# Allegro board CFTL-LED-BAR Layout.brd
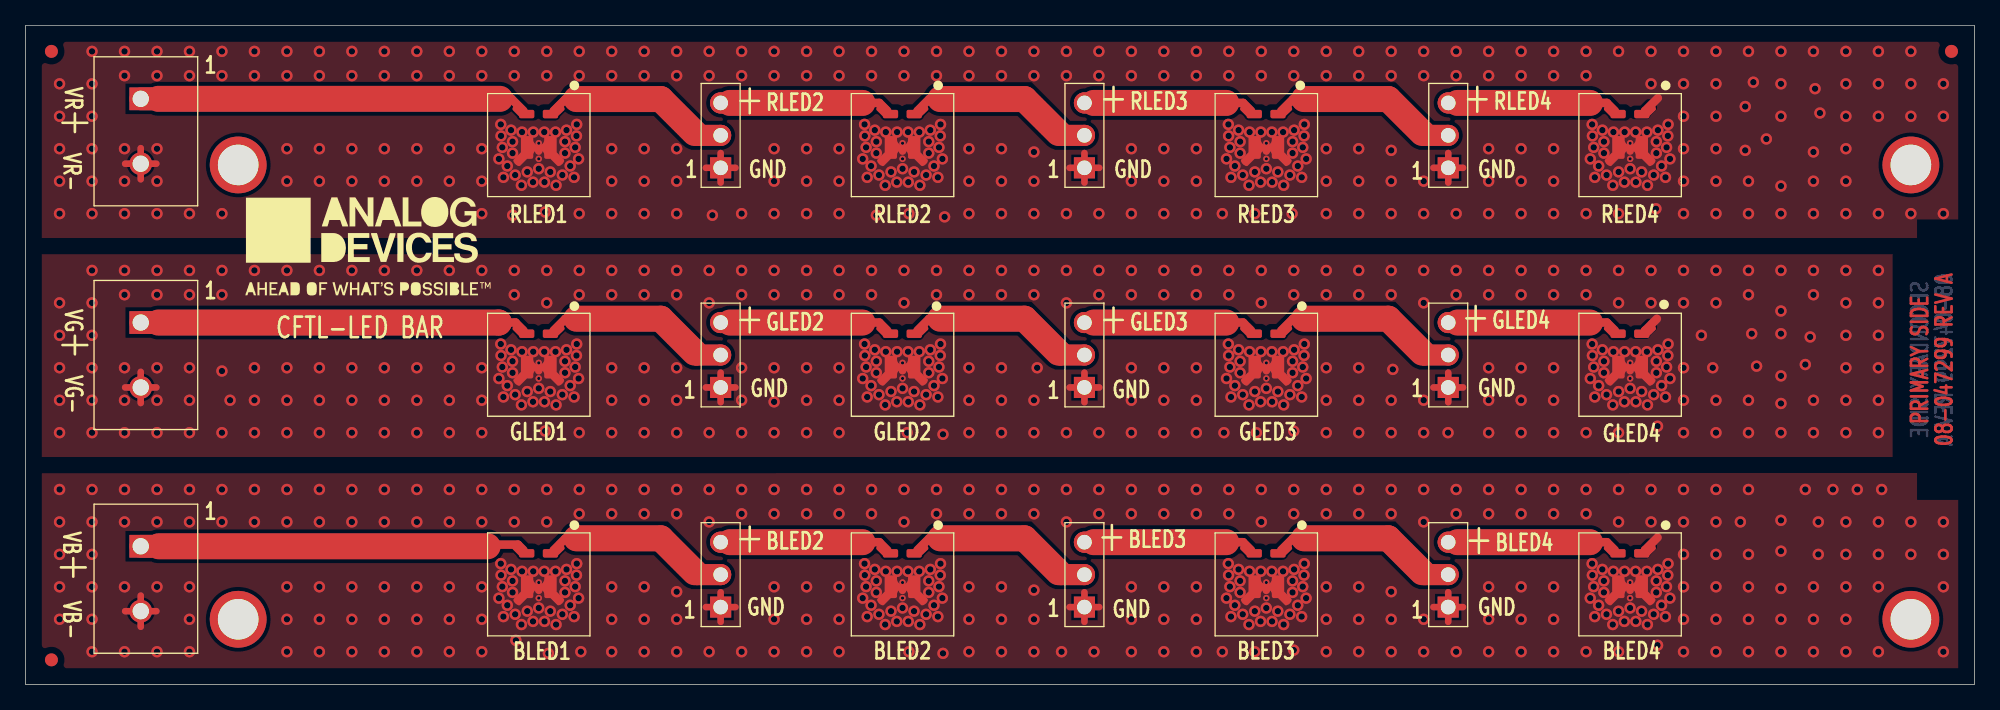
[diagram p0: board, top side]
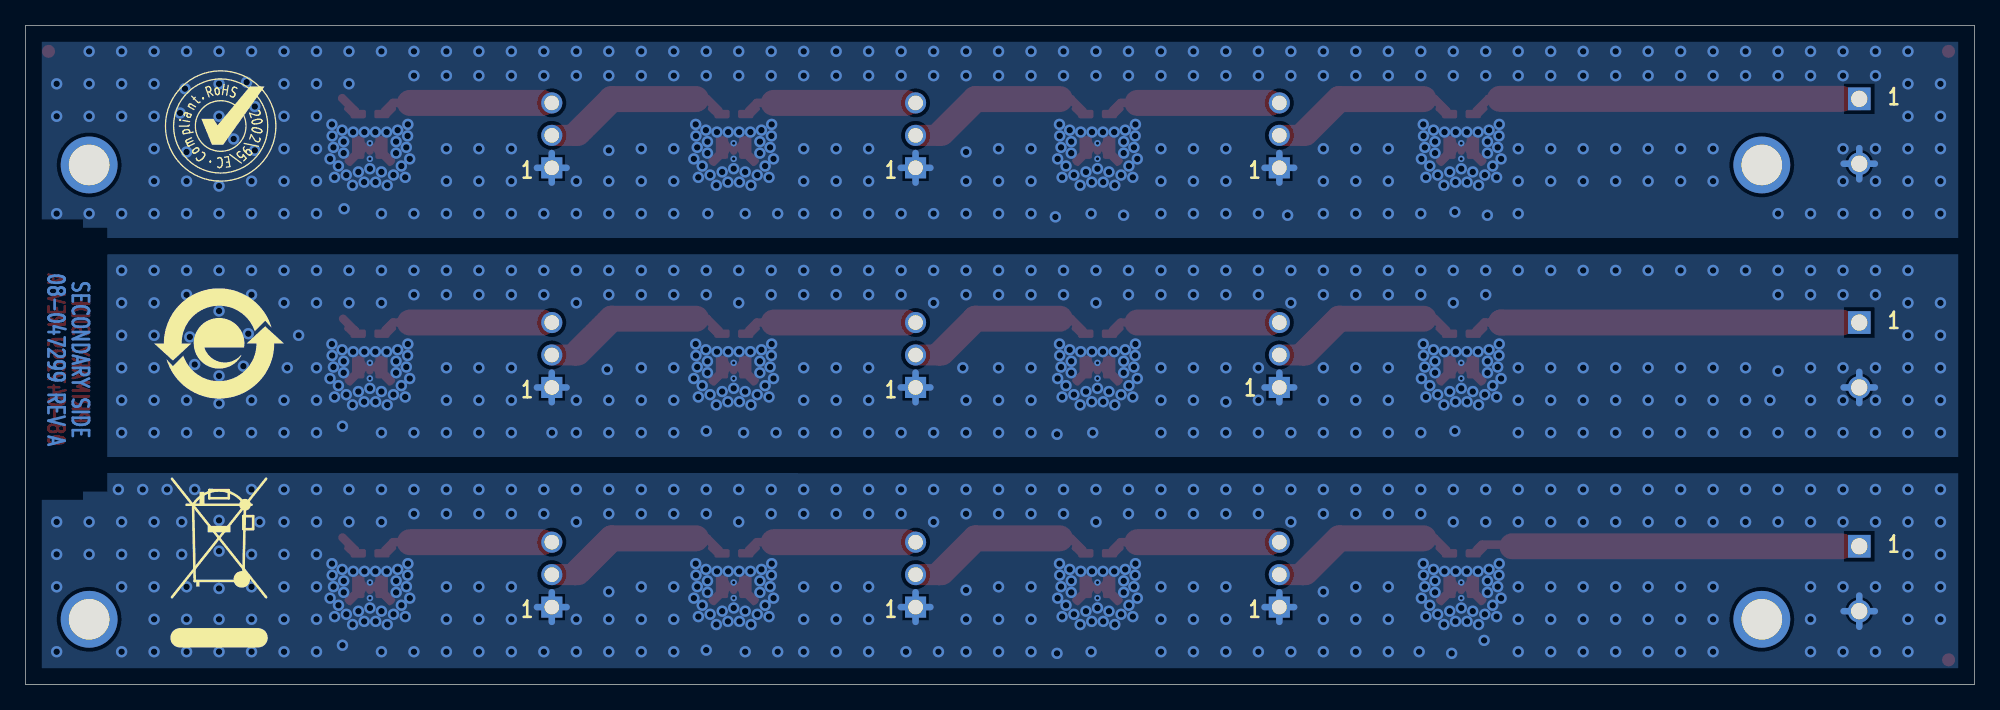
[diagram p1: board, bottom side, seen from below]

Outline 152.41 x 51.57 mm; copper layers: TOP, BOTTOM. Coordinates in mm from the lower left corner of the outline.
Outline path: 0,51.57 152.41,51.57 152.41,0 0,0 0,51.57

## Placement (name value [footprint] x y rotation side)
D1  LXM5-PD01  [LEDSML120W177H83]  40.13 42.98 180 top
D2  LXM5-PD01  [LEDSML120W177H83]  68.58 42.98 180 top
D3  LXM5-PD01  [LEDSML120W177H83]  97.03 42.98 180 top
D4  LXM5-PD01  [LEDSML120W177H83]  125.48 42.98 180 top
D5  LXML-PM01-0080  [LEDSML120W177H83]  40.13 25.79 180 top
D6  LXML-PM01-0080  [LEDSML120W177H83]  68.58 25.79 180 top
D7  LXML-PM01-0080  [LEDSML120W177H83]  97.03 25.79 180 top
D8  LXML-PM01-0080  [LEDSML120W177H83]  125.48 25.79 180 top
D9  LXML-PB02  [LEDSML120W177H83]  40.13 8.6 180 top
D10  LXML-PB02  [LEDSML120W177H83]  68.58 8.6 180 top
D11  LXML-PB02  [LEDSML120W177H83]  97.03 8.6 180 top
D12  LXML-PB02  [LEDSML120W177H83]  125.48 8.6 180 top
NOREF  -  []  9.01 5.74 0 top
NOREF#2  -  [unnamed#2]  150.61 49.55 0 top
NOREF#3  -  []  -52.27 360.6 0 top
NOREF#4  -  []  152.41 0.07 0 top
NOREF#5  -  [unnamed#2]  2.02 49.55 0 top
NOREF#6  -  []  -80.91 -47.44 0 top
NOREF#7  -  [unnamed#2]  16.63 5.1 0 top
NOREF#8  -  []  0 51.57 0 top
NOREF#9  -  []  152.41 0 90 top
NOREF#10  -  [unnamed#2]  147.44 5.1 0 top
NOREF#11  -  []  152.41 0 90 top
NOREF#12  -  []  0 0 0 top
NOREF#13  -  []  152.41 51.57 180 top
NOREF#14  -  []  -60.95 153.48 0 top
NOREF#15  -  [unnamed#2]  147.44 40.66 0 top
NOREF#16  -  []  10.41 306.69 0 top
NOREF#17  -  []  76.95 62.04 0 top
NOREF#18  -  []  97.41 140.45 0 top
NOREF#19  -  []  0 0 0 top
NOREF#20  -  []  0 51.57 0 top
NOREF#21  -  []  0 0 0 top
NOREF#22  -  [unnamed#2]  16.63 40.66 0 top
NOREF#23  -  [unnamed#2]  2.02 1.93 0 top
NOREF#24  -  []  26.8 34.28 0 top
NOREF#25  -  []  9.01 5.74 0 top
NOREF#26  -  []  0 51.57 270 top
NOREF#27  -  []  137.28 26.69 180 bottom
NOREF#28  -  []  128.01 19.78 180 bottom
NOREF#29  -  []  137.15 43.71 180 bottom
P1  OSTTC022162  [CNHDR1X2H406]  9.01 45.84 270 top
P2  TSW-103-23-F-S  [CNTHMHDR1X3L300W100H343]  54.36 40.44 90 top
P3  TSW-103-23-F-S  [CNTHMHDR1X3L300W100H343]  82.81 40.44 90 top
P4  TSW-103-23-F-S  [CNTHMHDR1X3L300W100H343]  111.26 40.44 90 top
P5  OSTTC022162  [CNHDR1X2H406]  9.01 28.33 270 top
P6  TSW-103-23-F-S  [CNTHMHDR1X3L300W100H343]  54.36 23.25 90 top
P7  TSW-103-23-F-S  [CNTHMHDR1X3L300W100H343]  82.81 23.25 90 top
P8  TSW-103-23-F-S  [CNTHMHDR1X3L300W100H343]  111.26 23.25 90 top
P9  OSTTC022162  [CNHDR1X2H406]  9.01 10.82 270 top
P10  TSW-103-23-F-S  [CNTHMHDR1X3L300W100H343]  54.36 6.06 90 top
P11  TSW-103-23-F-S  [CNTHMHDR1X3L300W100H343]  82.81 6.06 90 top
P12  TSW-103-23-F-S  [CNTHMHDR1X3L300W100H343]  111.25 6.06 90 top

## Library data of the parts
D1-D4 = DIOLED_3P_V9: User Part Number: UPN; Tolerance: N/A; alternate symbols: (LEDSML120W177H83_A); part number: DIOLED_3P_V9_SM-LXM5-PD01,2.1V,N/A,E024998,LEDSML120W177H83; tolerance: N/A
D5-D8 = DIOLED_3P_V9: User Part Number: UPN; Tolerance: N/A; alternate symbols: (LEDSML120W177H83_A); part number: DIOLED_3P_V9_SM-LXML-PM01-0080,2.9V,N/A,E024999,LEDSML120W177H83; tolerance: N/A
D9-D12 = DIOLED_3P_V9: User Part Number: UPN; Tolerance: N/A; alternate symbols: (LEDSML120W177H83_A); part number: DIOLED_3P_V9_SM-LXML-PB02,2.95V,N/A,E025000,LEDSML120W177H83; tolerance: N/A
P1 P5 P9 = CN2P: User Part Number: UPN; Tolerance: N/A; alternate symbols: (); part number: CN2P_TH-OSTTC022162,E016936,CNHDR1X2H406; tolerance: N/A
P2-P4 P6-P8 P10-P12 = CN3P: User Part Number: UPN; Tolerance: N/A; alternate symbols: (); part number: CN3P_TH-TSW-103-23-F-S,E027277,CNTHMHDR1X3L300W100H343; tolerance: N/A

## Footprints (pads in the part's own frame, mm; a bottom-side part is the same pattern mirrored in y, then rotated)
CNHDR1X2H406
  rect 1.778x1.778 hole 1.27: 1(0,0)
  round 1.778 hole 1.27: 2(5.08,0)
CNTHMHDR1X3L300W100H343
  rect 1.651x1.651 hole 1.143: 1(0,0)
  round 1.651 hole 1.143: 2(2.54,0) 3(5.08,0)
LEDSML120W177H83
  custom 0.292x0.292 smd: 1(-1.168,-1.92)
  custom 0.293x0.293 smd: 2(1.198,-1.924)
  custom 0.587x0.587 smd: 3(0,1.23)
unnamed#2
  round 1.016 smd: (0,0)

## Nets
AGND_A: D1.3(THERMAL) D2.3(THERMAL) D3.3(THERMAL) D4.1(C) D4.3(THERMAL) P1.2(N2) P2.1(N1) P3.1(N1) P4.1(N1)
AGND_B: D5.3(THERMAL) D6.3(THERMAL) D7.3(THERMAL) D8.1(C) D8.3(THERMAL) P5.2(N2) P6.1(N1) P7.1(N1) P8.1(N1)
AGND_C: D9.3(THERMAL) D10.3(THERMAL) D11.3(THERMAL) D12.1(C) D12.3(THERMAL) P9.2(N2) P10.1(N1) P11.1(N1) P12.1(N1)
UNNAMED_2_CN2P_I1_N1: D1.2(A) P1.1(N1)
UNNAMED_2_CN3P_I7_N2: D2.1(C) P3.2(N2)
UNNAMED_2_CN3P_I7_N3: D3.2(A) P3.3(N3)
UNNAMED_2_CN3P_I9_N2: D1.1(C) P2.2(N2)
UNNAMED_2_CN3P_I9_N3: D2.2(A) P2.3(N3)
UNNAMED_2_CN3P_I10_N2: D3.1(C) P4.2(N2)
UNNAMED_2_CN3P_I10_N3: D4.2(A) P4.3(N3)
UNNAMED_3_CN2P_I10_N1: D5.2(A) P5.1(N1)
UNNAMED_3_CN3P_I5_N2: D7.1(C) P8.2(N2)
UNNAMED_3_CN3P_I5_N3: D8.2(A) P8.3(N3)
UNNAMED_3_CN3P_I6_N2: D6.1(C) P7.2(N2)
UNNAMED_3_CN3P_I6_N3: D7.2(A) P7.3(N3)
UNNAMED_3_CN3P_I12_N2: D5.1(C) P6.2(N2)
UNNAMED_3_CN3P_I12_N3: D6.2(A) P6.3(N3)
UNNAMED_4_CN2P_I13_N1: D9.2(A) P9.1(N1)
UNNAMED_4_CN3P_I4_N2: D11.1(C) P12.2(N2)
UNNAMED_4_CN3P_I4_N3: D12.2(A) P12.3(N3)
UNNAMED_4_CN3P_I9_N2: D10.1(C) P11.2(N2)
UNNAMED_4_CN3P_I9_N3: D11.2(A) P11.3(N3)
UNNAMED_4_CN3P_I11_N2: D9.1(C) P10.2(N2)
UNNAMED_4_CN3P_I11_N3: D10.2(A) P10.3(N3)

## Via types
v1: diameter 0.889, hole 0.508, TOP to BOTTOM, 1124 vias
v2: diameter 0.508, hole 0.254, TOP to BOTTOM, 24 vias

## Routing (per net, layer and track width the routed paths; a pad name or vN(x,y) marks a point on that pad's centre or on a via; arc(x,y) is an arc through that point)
AGND_A: length 38.9
  TOP w0.508: 82.81,39.28 P3.1 ; P3.1 82.81,41.59 ; P3.1 83.96,40.44 ; P3.1 81.65,40.44 ; P2.1 55.51,40.44 ; P2.1 54.36,39.28 ; P2.1 53.2,40.44 ; P2.1 54.36,41.59 ; P1.2 10.23,40.76 ; P1.2 9.01,39.54 ; P1.2 9.01,41.98 ; P1.2 7.79,40.76 ; 110.1,40.44 P4.1 ; P4.1 112.41,40.44 ; P4.1 111.26,39.28 ; P4.1 111.26,41.59
  TOP w0.66: D4.1 126.65,44.9 127.65,45.89
  BOTTOM w0.508: P3.1 83.96,40.44 ; P3.1 82.81,41.59 ; P3.1 82.81,39.28 ; P3.1 81.65,40.44 ; P1.2 9.01,41.98 ; P1.2 9.01,39.54 ; P1.2 10.23,40.76 ; P1.2 7.79,40.76 ; P4.1 112.41,40.44 ; P4.1 111.26,41.59 ; P4.1 110.1,40.44 ; P4.1 111.26,39.28 ; P2.1 55.51,40.44 ; P2.1 53.2,40.44 ; P2.1 54.36,39.28 ; P2.1 54.36,41.59
  vias: v1(2.66,47.01) v1(2.66,44.47) v1(2.66,41.93) v1(2.66,39.39) v1(2.66,36.85) v1(5.2,49.55) v1(5.2,47.01) v1(5.2,44.47) v1(5.2,41.93) v1(5.2,39.39) v1(5.2,36.85) v1(7.74,49.55) v1(7.74,47.65) v1(7.74,41.93) v1(7.74,39.39) v1(7.74,36.85) v1(10.28,49.55) v1(10.28,47.65) v1(10.28,41.93) v1(10.28,39.39) v1(10.28,36.85) v1(12.82,49.55) v1(12.82,47.65) v1(12.82,36.85) v1(15.36,49.55) v1(15.36,47.65) v1(15.36,36.85) v1(17.9,49.55) v1(17.9,47.65) v1(20.44,49.55) v1(20.44,47.65) v1(20.44,41.93) v1(20.44,39.39) v1(22.98,49.55) v1(22.98,47.65) v1(22.98,41.93) v1(22.98,39.39) v1(25.52,49.55) v1(25.52,47.65) v1(25.52,41.93) v1(25.52,39.39) v1(28.06,49.55) v1(28.06,47.65) v1(28.06,41.93) v1(28.06,39.39) v1(30.6,49.55) v1(30.6,47.65) v1(30.6,41.93) v1(30.6,39.39) v1(33.14,49.55) v1(33.14,47.65) v1(33.14,41.93) v1(33.14,39.39) v1(35.68,49.55) v1(35.68,47.65) v1(35.68,41.93) v1(35.68,39.39) v1(35.68,36.85) v1(37.02,41.13) v1(37.16,43.83) v1(37.18,42.93) v1(37.28,42.03) v1(37.37,39.69) v1(37.67,40.58) v1(37.96,43.38) v1(38.08,42.48) v1(38.08,41.58) v1(38.09,36.72) v1(38.22,49.55) v1(38.22,47.65) v1(38.29,39.87) v1(38.82,43.23) v1(38.78,39.07) v1(39.23,40.11) v1(39.7,43.23) v1(39.68,39.31) v1(40.13,40.36) v1(40.56,43.23) v1(40.58,39.31) v1(40.63,36.98) v1(40.76,49.55) v1(40.76,47.65) v1(41.03,40.11) v1(41.44,43.23) v1(41.49,39.07) v1(41.98,39.87) v1(42.18,42.48) v1(42.18,41.58) v1(42.3,43.38) v1(42.59,40.58) v1(42.9,39.69) v1(42.98,42.03) v1(43.1,43.83) v1(43.08,42.93) v1(43.25,41.13) v1(43.3,49.55) v1(43.3,47.65) v1(43.3,36.85) v1(45.84,49.55) v1(45.84,47.65) v1(45.84,41.93) v1(45.84,39.39) v1(45.84,36.85) v1(48.38,49.55) v1(48.38,47.65) v1(48.38,41.93) v1(48.38,39.39) v1(48.38,36.85) v1(50.92,49.55) v1(50.92,47.65) v1(50.92,41.93) v1(50.92,39.39) v1(50.92,36.85) v1(53.46,49.55) v1(53.46,47.65) v1(53.71,36.72) v1(56,49.55) v1(56,47.65) v1(56,36.85) v1(58.54,49.55) v1(58.54,47.65) v1(58.54,41.93) v1(58.54,39.39) v1(58.54,36.85) v1(61.08,49.55) v1(61.08,47.65) v1(61.08,41.93) v1(61.08,39.39) v1(61.08,36.85) v1(63.62,49.55) v1(63.62,47.65) v1(63.62,41.93) v1(63.62,39.39) v1(63.62,36.85) v1(65.47,41.13) v1(65.61,43.83) v1(65.63,42.93) v1(65.73,42.03) v1(65.82,39.69) v1(66.16,49.55) v1(66.16,47.65) v1(66.12,40.58) v1(66.41,43.38) v1(66.53,42.48) v1(66.53,41.58) v1(66.54,36.72) v1(66.74,39.87) v1(67.23,39.07) v1(67.27,43.23) v1(67.68,40.11) v1(68.15,43.23) v1(68.13,39.31) v1(68.58,40.36) v1(68.7,49.55) v1(68.7,47.65) v1(69.01,43.23) v1(69.03,39.31) v1(69.08,36.85) v1(69.48,40.11) v1(69.89,43.23) v1(69.94,39.07) v1(70.43,39.87) v1(70.63,42.48) v1(70.63,41.58) v1(70.75,43.38) v1(71.04,40.58) v1(71.24,49.55) v1(71.24,47.65) v1(71.35,39.69) v1(71.43,42.03) v1(71.55,43.83) v1(71.53,42.93) v1(71.7,41.13) v1(71.87,36.6) v1(73.78,49.55) v1(73.78,47.65) v1(73.78,41.93) v1(73.78,39.39) v1(73.78,36.85) v1(76.32,49.55) v1(76.32,47.65) v1(76.32,41.93) v1(76.32,39.39) v1(76.32,36.85) v1(78.86,49.55) v1(78.86,47.65) v1(78.86,41.68) v1(78.86,39.39) v1(78.86,36.85) v1(81.4,49.55) v1(81.4,47.65) v1(81.4,36.85) v1(83.94,49.55) v1(83.94,47.65) v1(83.94,36.85) v1(86.48,49.55) v1(86.48,47.65) v1(86.48,41.93) v1(86.48,39.39) v1(86.48,36.85) v1(89.02,49.55) v1(89.02,47.65) v1(89.02,41.93) v1(89.02,39.39) v1(89.02,36.85) v1(91.56,49.55) v1(91.56,47.65) v1(91.56,41.93) v1(91.56,39.39) v1(91.56,36.85) v1(93.59,36.85) v1(93.92,41.13) v1(94.1,49.55) v1(94.1,47.65) v1(94.06,43.83) v1(94.08,42.93) v1(94.18,42.03) v1(94.27,39.69) v1(94.57,40.58) v1(94.86,43.38) v1(94.98,42.48) v1(94.98,41.58) v1(95.19,39.87) v1(95.72,43.23) v1(95.68,39.07) v1(96.13,40.11) v1(96.13,36.85) v1(96.64,49.55) v1(96.64,47.65) v1(96.6,43.23) v1(96.58,39.31) v1(97.03,40.36) v1(97.46,43.23) v1(97.48,39.31) v1(97.93,40.11) v1(98.34,43.23) v1(98.39,39.07) v1(98.88,39.87) v1(99.05,36.85) v1(99.08,42.48) v1(99.08,41.58) v1(99.18,49.55) v1(99.18,47.65) v1(99.2,43.38) v1(99.49,40.58) v1(99.8,39.69) v1(99.88,42.03) v1(100,43.83) v1(99.98,42.93) v1(100.15,41.13) v1(101.72,49.55) v1(101.72,47.65) v1(101.72,41.93) v1(101.72,39.39) v1(101.72,36.85) v1(104.26,49.55) v1(104.26,47.65) v1(104.26,41.93) v1(104.26,39.39) v1(104.26,36.85) v1(106.8,49.55) v1(106.8,47.65) v1(106.8,41.8) v1(106.8,39.39) v1(106.8,36.85) v1(109.34,49.55) v1(109.34,47.65) v1(109.34,39.39) v1(109.34,36.85) v1(111.88,49.55) v1(111.88,47.65) v1(111.88,36.85) v1(114.42,49.55) v1(114.42,47.65) v1(114.42,41.93) v1(114.42,39.39) v1(114.42,36.85) v1(116.96,49.55) v1(116.96,47.65) v1(116.96,41.93) v1(116.96,39.39) v1(116.96,36.85) v1(119.5,49.55) v1(119.5,47.65) v1(119.5,41.93) v1(119.5,39.39) v1(119.5,36.85) v1(122.04,49.55) v1(122.04,47.65) v1(122.04,36.85) v1(122.37,41.13) v1(122.51,43.83) v1(122.53,42.93) v1(122.63,42.03) v1(122.72,39.69) v1(123.02,40.58) v1(123.31,43.38) v1(123.43,42.48) v1(123.43,41.58) v1(123.64,39.87) v1(124.13,39.07) v1(124.17,43.23) v1(124.58,49.55) v1(124.58,40.11) v1(124.58,36.85) v1(125.05,43.23) v1(125.03,39.31) v1(125.48,40.36) v1(125.91,43.23) v1(125.93,39.31) v1(126.38,40.11) v1(126.79,43.23) v1(126.84,39.07) v1(127.12,49.55) v1(127.12,47.01) v1(127.33,39.87) v1(127.53,42.48) v1(127.53,41.58) v1(127.5,37.23) v1(127.65,43.38) v1(127.94,40.58) v1(128.25,39.69) v1(128.33,42.03) v1(128.45,43.83) v1(128.43,42.93) v1(128.6,41.13) v1(129.66,49.55) v1(129.66,47.01) v1(129.66,44.47) v1(129.66,41.93) v1(129.66,39.39) v1(129.66,36.85) v1(132.2,49.55) v1(132.2,47.01) v1(132.2,44.47) v1(132.2,41.93) v1(132.2,39.39) v1(132.2,36.85) v1(134.48,45.23) v1(134.48,41.8) v1(134.74,49.55) v1(134.74,39.39) v1(134.74,36.85) v1(135.12,47.14) v1(136.13,42.69) v1(137.28,49.55) v1(137.28,47.01) v1(137.28,44.47) v1(137.28,39.01) v1(137.28,36.85) v1(139.82,49.55) v1(139.82,41.68) v1(139.82,39.39) v1(139.82,36.85) v1(139.94,46.63) v1(140.33,44.72) v1(142.36,49.55) v1(142.36,47.01) v1(142.36,44.47) v1(142.36,41.93) v1(142.36,39.39) v1(142.36,36.85) v1(144.9,49.55) v1(144.9,47.01) v1(144.9,44.47) v1(144.9,36.85) v1(147.44,49.55) v1(147.44,47.01) v1(147.44,44.47) v1(147.44,36.85) v1(149.98,47.01) v1(149.98,44.47) v1(149.98,36.85) v2(40.13,42.36) v2(40.13,41.14) v2(68.58,42.36) v2(68.58,41.14) v2(97.03,42.36) v2(97.03,41.14) v2(125.48,42.36) v2(125.48,41.14)
AGND_B: length 38.8
  TOP w0.508: 110.1,23.25 P8.1 ; P8.1 111.26,22.09 ; P8.1 112.41,23.25 ; P8.1 111.26,24.4 ; P5.2 9.01,24.47 ; P5.2 10.23,23.25 ; P5.2 9.01,22.03 ; P5.2 7.79,23.25 ; 82.81,22.09 P7.1 ; P7.1 81.65,23.25 ; P7.1 82.81,24.4 ; P7.1 83.96,23.25 ; P6.1 54.36,24.4 ; P6.1 53.2,23.25 ; P6.1 54.36,22.09 ; P6.1 55.51,23.25
  TOP w0.66: D8.1 126.66,27.71 127.57,28.62
  BOTTOM w0.508: P6.1 55.51,23.25 ; P6.1 54.36,24.4 ; P6.1 53.2,23.25 ; P6.1 54.36,22.09 ; 81.65,23.25 P7.1 ; P7.1 83.96,23.25 ; P7.1 82.81,22.09 ; P7.1 82.81,24.4 ; P8.1 111.26,24.4 ; P8.1 111.26,22.09 ; P8.1 110.1,23.25 ; P8.1 112.41,23.25 ; P5.2 9.01,24.47 ; P5.2 7.79,23.25 ; P5.2 10.23,23.25 ; P5.2 9.01,22.03
  vias: v1(2.66,29.87) v1(2.66,27.33) v1(2.66,24.79) v1(2.66,22.25) v1(2.66,19.71) v1(5.2,32.41) v1(5.2,29.87) v1(5.2,27.33) v1(5.2,24.79) v1(5.2,22.25) v1(5.2,19.71) v1(7.74,32.41) v1(7.74,30.5) v1(7.74,24.79) v1(7.74,22.25) v1(7.74,19.71) v1(10.28,32.41) v1(10.28,30.5) v1(10.28,24.79) v1(10.28,22.25) v1(10.28,19.71) v1(12.82,32.41) v1(12.82,30.5) v1(12.82,24.79) v1(12.82,22.25) v1(12.82,19.71) v1(15.36,32.41) v1(15.36,30.5) v1(15.36,24.53) v1(15.36,19.71) v1(15.99,22.25) v1(17.9,32.41) v1(17.9,24.79) v1(17.9,22.25) v1(17.9,19.71) v1(20.44,32.41) v1(20.44,24.79) v1(20.44,22.25) v1(20.44,19.71) v1(22.98,32.41) v1(22.98,24.79) v1(22.98,22.25) v1(22.98,19.71) v1(25.52,32.41) v1(25.52,24.79) v1(25.52,22.25) v1(25.52,19.71) v1(28.06,32.41) v1(28.06,24.79) v1(28.06,22.25) v1(28.06,19.71) v1(30.6,32.41) v1(30.6,24.79) v1(30.6,22.25) v1(30.6,19.71) v1(33.14,32.41) v1(33.14,24.79) v1(33.14,22.25) v1(33.14,19.71) v1(35.68,32.41) v1(35.68,24.79) v1(35.68,22.25) v1(35.68,19.71) v1(37.02,23.94) v1(37.16,26.64) v1(37.18,25.74) v1(37.28,24.84) v1(37.37,22.5) v1(37.67,23.39) v1(37.96,26.19) v1(38.08,25.29) v1(38.08,24.39) v1(38.22,32.41) v1(38.22,30.5) v1(38.29,22.68) v1(38.82,26.04) v1(38.78,21.88) v1(39.23,22.92) v1(39.7,26.04) v1(39.68,22.12) v1(40.13,23.17) v1(40.56,26.04) v1(40.58,22.12) v1(40.63,19.83) v1(40.76,32.41) v1(40.76,29.87) v1(41.03,22.92) v1(41.44,26.04) v1(41.49,21.88) v1(41.98,22.68) v1(42.18,25.29) v1(42.18,24.39) v1(42.3,26.19) v1(42.59,23.39) v1(42.9,22.5) v1(42.98,24.84) v1(43.1,26.64) v1(43.08,25.74) v1(43.25,23.94) v1(43.3,32.41) v1(43.3,30.5) v1(43.3,19.71) v1(45.84,32.41) v1(45.84,30.5) v1(45.84,24.79) v1(45.84,22.25) v1(45.84,19.71) v1(48.38,32.41) v1(48.38,30.5) v1(48.38,24.79) v1(48.38,22.25) v1(48.38,19.71) v1(50.92,32.41) v1(50.92,30.5) v1(50.92,24.79) v1(50.92,22.25) v1(50.92,19.71) v1(53.46,32.41) v1(53.46,29.87) v1(53.46,19.71) v1(56,32.41) v1(56,30.5) v1(56,24.79) v1(56,22.25) v1(56,19.71) v1(58.54,32.41) v1(58.54,30.5) v1(58.54,24.79) v1(58.54,22.12) v1(58.54,19.71) v1(61.08,32.41) v1(61.08,30.5) v1(61.08,24.79) v1(61.08,22.25) v1(61.08,19.71) v1(63.62,32.41) v1(63.62,30.5) v1(63.62,24.79) v1(63.62,22.25) v1(63.62,19.71) v1(65.47,23.94) v1(65.61,26.64) v1(65.63,25.74) v1(65.73,24.84) v1(65.82,22.5) v1(66.16,32.41) v1(66.16,30.5) v1(66.12,23.39) v1(66.41,26.19) v1(66.53,25.29) v1(66.53,24.39) v1(66.74,22.68) v1(67.23,21.88) v1(67.27,26.04) v1(67.68,22.92) v1(68.15,26.04) v1(68.13,22.12) v1(68.58,23.17) v1(68.7,32.41) v1(68.7,29.87) v1(68.95,19.71) v1(69.01,26.04) v1(69.03,22.12) v1(69.48,22.92) v1(69.89,26.04) v1(69.94,21.88) v1(70.43,22.68) v1(70.63,25.29) v1(70.63,24.39) v1(70.75,26.19) v1(71.04,23.39) v1(71.24,32.41) v1(71.24,30.5) v1(71.35,22.5) v1(71.43,24.84) v1(71.55,26.64) v1(71.53,25.74) v1(71.7,23.94) v1(71.75,19.58) v1(73.78,32.41) v1(73.78,30.5) v1(73.78,24.79) v1(73.78,22.25) v1(73.78,19.71) v1(76.32,32.41) v1(76.32,30.5) v1(76.32,24.79) v1(76.32,22.25) v1(76.32,19.71) v1(78.86,32.41) v1(78.86,30.5) v1(78.86,22.25) v1(78.86,19.71) v1(79.11,24.79) v1(81.4,32.41) v1(81.4,29.87) v1(81.4,19.71) v1(83.94,32.41) v1(83.94,30.5) v1(83.94,19.71) v1(86.48,32.41) v1(86.48,30.5) v1(86.48,24.79) v1(86.48,22.25) v1(86.48,19.71) v1(89.02,32.41) v1(89.02,30.5) v1(89.02,24.79) v1(89.02,22.25) v1(89.02,19.71) v1(91.56,32.41) v1(91.56,30.5) v1(91.56,24.79) v1(91.56,22.25) v1(91.56,19.71) v1(93.72,19.71) v1(93.92,23.94) v1(94.1,32.41) v1(94.1,30.5) v1(94.06,26.64) v1(94.08,25.74) v1(94.18,24.84) v1(94.27,22.5) v1(94.57,23.39) v1(94.86,26.19) v1(94.98,25.29) v1(94.98,24.39) v1(95.19,22.68) v1(95.72,26.04) v1(95.68,21.88) v1(96.13,22.92) v1(96.26,19.71) v1(96.64,32.41) v1(96.64,29.87) v1(96.6,26.04) v1(96.58,22.12) v1(97.03,23.17) v1(97.46,26.04) v1(97.48,22.12) v1(97.93,22.92) v1(98.34,26.04) v1(98.39,21.88) v1(98.88,22.68) v1(99.08,25.29) v1(99.08,24.39) v1(99.18,32.41) v1(99.18,30.5) v1(99.2,26.19) v1(99.18,19.83) v1(99.49,23.39) v1(99.8,22.5) v1(99.88,24.84) v1(100,26.64) v1(99.98,25.74) v1(100.15,23.94) v1(101.72,32.41) v1(101.72,30.5) v1(101.72,24.79) v1(101.72,22.25) v1(101.72,19.71) v1(104.26,32.41) v1(104.26,30.5) v1(104.26,24.79) v1(104.26,22.25) v1(104.26,19.71) v1(106.8,32.41) v1(106.8,30.5) v1(106.8,22.25) v1(106.8,19.71) v1(106.92,24.66) v1(109.34,32.41) v1(109.34,29.87) v1(109.34,22.25) v1(109.34,19.71) v1(111.24,19.71) v1(111.88,32.41) v1(111.88,30.5) v1(114.42,32.41) v1(114.42,30.5) v1(114.42,24.79) v1(114.42,22.25) v1(114.42,19.71) v1(116.96,32.41) v1(116.96,30.5) v1(116.96,24.79) v1(116.96,22.25) v1(116.96,19.71) v1(119.5,32.41) v1(119.5,30.5) v1(119.5,24.79) v1(119.5,22.25) v1(119.5,19.71) v1(122.04,32.41) v1(122.04,30.5) v1(122.04,19.71) v1(122.37,23.94) v1(122.51,26.64) v1(122.53,25.74) v1(122.63,24.84) v1(122.72,22.5) v1(123.02,23.39) v1(123.31,26.19) v1(123.43,25.29) v1(123.43,24.39) v1(123.64,22.68) v1(124.13,21.88) v1(124.17,26.04) v1(124.58,32.41) v1(124.58,29.87) v1(124.58,22.92) v1(124.58,19.71) v1(125.05,26.04) v1(125.03,22.12) v1(125.48,23.17) v1(125.91,26.04) v1(125.93,22.12) v1(126.38,22.92) v1(126.79,26.04) v1(126.84,21.88) v1(127.12,32.41) v1(127.12,29.87) v1(127.33,22.68) v1(127.53,25.29) v1(127.53,24.39) v1(127.65,26.19) v1(127.63,20.21) v1(127.94,23.39) v1(128.25,22.5) v1(128.33,24.84) v1(128.45,26.64) v1(128.43,25.74) v1(128.6,23.94) v1(129.66,32.41) v1(129.66,29.87) v1(129.66,24.79) v1(129.66,22.25) v1(129.66,19.71) v1(131.05,27.33) v1(131.94,24.79) v1(132.2,32.41) v1(132.2,29.87) v1(132.2,22.25) v1(132.2,19.71) v1(134.74,32.41) v1(134.74,30.5) v1(134.74,22.25) v1(134.74,19.71) v1(134.99,27.45) v1(135.37,24.91) v1(137.28,32.41) v1(137.28,29.23) v1(137.28,27.45) v1(137.28,24.15) v1(137.28,21.99) v1(137.28,19.71) v1(139.18,25.04) v1(139.56,27.2) v1(139.82,32.41) v1(139.82,30.5) v1(139.82,22.25) v1(139.82,19.71) v1(142.36,32.41) v1(142.36,29.87) v1(142.36,27.33) v1(142.36,24.79) v1(142.36,22.25) v1(142.36,19.71) v1(144.9,32.41) v1(144.9,29.87) v1(144.9,27.33) v1(144.9,24.79) v1(144.9,22.25) v1(144.9,19.71) v2(40.13,25.17) v2(40.13,23.95) v2(68.58,25.17) v2(68.58,23.95) v2(97.03,25.17) v2(97.03,23.95) v2(125.48,25.17) v2(125.48,23.95)
AGND_C: length 38.9
  TOP w0.508: 111.25,4.9 P12.1 ; P12.1 112.41,6.06 ; P12.1 110.1,6.06 ; P12.1 111.25,7.21 ; P9.2 10.23,5.74 ; P9.2 9.01,4.52 ; P9.2 9.01,6.95 ; P9.2 7.79,5.74 ; P10.1 55.51,6.06 ; P10.1 54.36,4.9 ; P10.1 54.36,7.21 ; P10.1 53.2,6.06 ; P11.1 83.96,6.06 ; P11.1 82.81,7.21 ; P11.1 82.81,4.9 ; P11.1 81.65,6.06
  TOP w0.66: 127.63,11.5 126.64,10.52 D12.1
  BOTTOM w0.508: P10.1 54.36,7.21 ; P10.1 54.36,4.9 ; P10.1 55.51,6.06 ; P10.1 53.2,6.06 ; P12.1 112.41,6.06 ; P12.1 111.25,7.21 ; P12.1 110.1,6.06 ; P12.1 111.25,4.9 ; P11.1 82.81,7.21 ; P11.1 82.81,4.9 ; P11.1 83.96,6.06 ; P11.1 81.65,6.06 ; 7.79,5.74 P9.2 ; P9.2 9.01,6.95 ; P9.2 9.01,4.52 ; P9.2 10.23,5.74
  vias: v1(2.66,15.26) v1(2.66,12.72) v1(2.66,10.18) v1(2.66,7.64) v1(2.66,5.1) v1(5.2,15.26) v1(5.2,12.72) v1(5.2,10.18) v1(5.2,7.64) v1(5.2,5.1) v1(5.2,2.56) v1(7.74,15.26) v1(7.74,12.72) v1(7.74,7.64) v1(7.74,2.56) v1(10.28,15.26) v1(10.28,12.72) v1(10.28,7.64) v1(10.28,2.56) v1(12.82,15.26) v1(12.82,12.72) v1(12.82,7.64) v1(12.82,5.1) v1(12.82,2.56) v1(15.36,15.26) v1(15.36,12.72) v1(17.9,15.26) v1(17.9,12.72) v1(20.44,15.26) v1(20.44,12.72) v1(20.44,7.64) v1(20.44,5.1) v1(20.44,2.56) v1(22.98,15.26) v1(22.98,12.72) v1(22.98,7.64) v1(22.98,5.1) v1(22.98,2.56) v1(25.52,15.26) v1(25.52,12.72) v1(25.52,7.64) v1(25.52,5.1) v1(25.52,2.56) v1(28.06,15.26) v1(28.06,12.72) v1(28.06,7.64) v1(28.06,5.1) v1(28.06,2.56) v1(30.6,15.26) v1(30.6,12.72) v1(30.6,7.64) v1(30.6,5.1) v1(30.6,2.56) v1(33.14,15.26) v1(33.14,12.72) v1(33.14,7.64) v1(33.14,5.1) v1(33.14,2.56) v1(35.68,15.26) v1(35.68,12.72) v1(35.68,7.64) v1(35.68,5.1) v1(35.68,2.56) v1(37.02,6.75) v1(37.16,9.45) v1(37.18,8.55) v1(37.28,7.65) v1(37.37,5.31) v1(37.67,6.2) v1(37.96,9) v1(38.08,8.1) v1(38.08,7.2) v1(38.22,15.26) v1(38.22,12.72) v1(38.29,5.49) v1(38.34,3.45) v1(38.82,8.85) v1(38.78,4.69) v1(39.23,5.73) v1(39.7,8.85) v1(39.68,4.93) v1(40.13,5.98) v1(40.56,8.85) v1(40.58,4.93) v1(40.76,15.26) v1(40.76,12.72) v1(40.88,2.43) v1(41.03,5.73) v1(41.44,8.85) v1(41.49,4.69) v1(41.98,5.49) v1(42.18,8.1) v1(42.18,7.2) v1(42.3,9) v1(42.59,6.2) v1(42.9,5.31) v1(42.98,7.65) v1(43.1,9.45) v1(43.08,8.55) v1(43.25,6.75) v1(43.3,15.26) v1(43.3,13.36) v1(43.42,2.56) v1(45.84,15.26) v1(45.84,13.36) v1(45.84,7.64) v1(45.84,5.1) v1(45.84,2.56) v1(48.38,15.26) v1(48.38,13.36) v1(48.38,7.64) v1(48.38,5.1) v1(48.38,2.56) v1(50.92,15.26) v1(50.92,13.36) v1(50.92,7.26) v1(50.92,5.1) v1(50.92,2.56) v1(53.46,15.26) v1(53.46,12.72) v1(53.46,2.56) v1(56,15.26) v1(56,13.36) v1(56,2.56) v1(58.54,15.26) v1(58.54,13.36) v1(58.54,7.64) v1(58.54,5.1) v1(58.54,2.56) v1(61.08,15.26) v1(61.08,13.36) v1(61.08,7.64) v1(61.08,5.1) v1(61.08,2.56) v1(63.62,15.26) v1(63.62,13.36) v1(63.62,7.64) v1(63.62,5.1) v1(63.62,2.56) v1(65.47,6.75) v1(65.61,9.45) v1(65.63,8.55) v1(65.73,7.65) v1(65.82,5.31) v1(66.16,15.26) v1(66.16,13.36) v1(66.12,6.2) v1(66.41,9) v1(66.53,8.1) v1(66.53,7.2) v1(66.74,5.49) v1(67.23,4.69) v1(67.27,8.85) v1(67.68,5.73) v1(68.15,8.85) v1(68.13,4.93) v1(68.58,5.98) v1(68.7,15.26) v1(68.7,12.72) v1(69.01,8.85) v1(69.03,4.93) v1(69.08,2.56) v1(69.48,5.73) v1(69.89,8.85) v1(69.94,4.69) v1(70.42,5.49) v1(70.63,8.1) v1(70.63,7.2) v1(70.75,9) v1(71.04,6.2) v1(71.24,15.26) v1(71.24,13.36) v1(71.35,5.31) v1(71.43,7.65) v1(71.55,9.45) v1(71.53,8.55) v1(71.7,6.75) v1(71.75,2.43) v1(73.78,15.26) v1(73.78,13.36) v1(73.78,7.64) v1(73.78,5.1) v1(73.78,2.56) v1(76.32,15.26) v1(76.32,13.36) v1(76.32,7.64) v1(76.32,5.1) v1(76.32,2.56) v1(78.86,15.26) v1(78.86,13.36) v1(78.86,7.39) v1(78.86,5.1) v1(78.86,2.56) v1(81.02,2.56) v1(81.4,15.26) v1(81.4,12.72) v1(83.56,2.56) v1(83.94,15.26) v1(83.94,13.36) v1(86.48,15.26) v1(86.48,13.36) v1(86.48,7.64) v1(86.48,5.1) v1(86.48,2.56) v1(89.02,15.26) v1(89.02,13.36) v1(89.02,7.64) v1(89.02,5.1) v1(89.02,2.56) v1(91.56,15.26) v1(91.56,13.36) v1(91.56,7.64) v1(91.56,5.1) v1(91.56,2.56) v1(93.59,2.56) v1(93.91,6.75) v1(94.1,15.26) v1(94.1,13.36) v1(94.06,9.45) v1(94.08,8.55) v1(94.18,7.65) v1(94.26,5.31) v1(94.57,6.2) v1(94.86,9) v1(94.98,8.1) v1(94.98,7.2) v1(95.19,5.49) v1(95.72,8.85) v1(95.67,4.69) v1(96.13,5.73) v1(96.13,2.56) v1(96.64,15.26) v1(96.64,12.72) v1(96.6,8.85) v1(96.58,4.93) v1(97.03,5.98) v1(97.46,8.85) v1(97.48,4.93) v1(97.93,5.73) v1(98.34,8.85) v1(98.38,4.69) v1(98.87,5.49) v1(99.08,8.1) v1(99.08,7.2) v1(99.18,15.26) v1(99.18,13.36) v1(99.2,9) v1(99.18,2.69) v1(99.49,6.2) v1(99.79,5.31) v1(99.88,7.65) v1(100,9.45) v1(99.98,8.55) v1(100.14,6.75) v1(101.72,15.26) v1(101.72,13.36) v1(101.72,7.64) v1(101.72,5.1) v1(101.72,2.56) v1(104.26,15.26) v1(104.26,13.36) v1(104.26,7.64) v1(104.26,5.1) v1(104.26,2.56) v1(106.8,15.26) v1(106.8,13.36) v1(106.8,7.26) v1(106.8,5.1) v1(106.8,2.56) v1(109.34,15.26) v1(109.34,12.72) v1(109.34,5.1) v1(109.34,2.56) v1(111.88,15.26) v1(111.88,13.36) v1(111.88,2.56) v1(114.42,15.26) v1(114.42,13.36) v1(114.42,7.64) v1(114.42,5.1) v1(114.42,2.56) v1(116.96,15.26) v1(116.96,13.36) v1(116.96,7.64) v1(116.96,5.1) v1(116.96,2.56) v1(119.5,15.26) v1(119.5,13.36) v1(119.5,7.64) v1(119.5,5.1) v1(119.5,2.56) v1(122.04,15.26) v1(122.04,13.36) v1(122.04,2.56) v1(122.36,6.75) v1(122.51,9.45) v1(122.53,8.55) v1(122.63,7.65) v1(122.71,5.31) v1(123.02,6.2) v1(123.31,9) v1(123.43,8.1) v1(123.43,7.2) v1(123.63,5.49) v1(124.12,4.69) v1(124.17,8.85) v1(124.58,15.26) v1(124.58,12.72) v1(124.58,5.73) v1(124.58,2.56) v1(125.05,8.85) v1(125.03,4.93) v1(125.48,5.98) v1(125.91,8.85) v1(125.93,4.93) v1(126.38,5.73) v1(126.79,8.85) v1(126.83,4.69) v1(127.12,15.26) v1(127.12,12.72) v1(127.32,5.49) v1(127.53,8.1) v1(127.53,7.2) v1(127.65,9) v1(127.63,3.07) v1(127.94,6.2) v1(128.24,5.31) v1(128.33,7.65) v1(128.45,9.45) v1(128.43,8.55) v1(128.59,6.75) v1(129.66,15.26) v1(129.66,12.72) v1(129.66,10.18) v1(129.66,7.64) v1(129.66,5.1) v1(129.66,2.56) v1(132.2,15.26) v1(132.2,12.72) v1(132.2,10.18) v1(132.2,7.64) v1(132.2,5.1) v1(132.2,2.56) v1(134.1,12.72) v1(134.74,15.26) v1(134.74,10.18) v1(134.74,7.64) v1(134.74,5.1) v1(134.74,2.56) v1(137.28,12.85) v1(137.28,10.43) v1(137.28,7.51) v1(137.28,5.1) v1(137.28,2.56) v1(139.18,15.26) v1(139.82,7.64) v1(139.82,5.1) v1(139.82,2.56) v1(140.2,12.72) v1(140.2,10.18) v1(141.34,15.26) v1(142.36,12.72) v1(142.36,10.18) v1(142.36,7.64) v1(142.36,5.1) v1(142.36,2.56) v1(143.25,15.26) v1(144.9,12.72) v1(144.9,10.18) v1(144.9,7.64) v1(144.9,2.56) v1(145.15,15.26) v1(147.44,12.72) v1(147.44,10.18) v1(149.98,12.72) v1(149.98,10.18) v1(149.98,7.64) v1(149.98,2.56) v2(40.13,7.98) v2(40.13,6.76) v2(68.58,7.98) v2(68.58,6.76) v2(97.03,7.98) v2(97.03,6.76) v2(125.48,7.98) v2(125.48,6.76)
UNNAMED_2_CN2P_I1_N1: length 30.3
  TOP w0.66: 37.1,45.84 38,45.84 D1.2
  TOP w1.778: 10.38,45.84 P1.1
  TOP w2.032: 37.1,45.84 10.38,45.84
UNNAMED_2_CN3P_I7_N2: length 14.6
  TOP w0.66: D2.1 70.67,45.82 71.53,45.82
  TOP w1.651: 80.77,43.17 80.96,42.98 P3.2
  TOP w2.032: 80.77,43.17 78.12,45.82 71.53,45.82
UNNAMED_2_CN3P_I7_N3: length 13.3
  TOP w0.66: 93.9,45.52 95.22,45.52 D3.2
  TOP w1.651: 83.53,45.52 P3.3
  TOP w2.032: 93.9,45.52 83.53,45.52
UNNAMED_2_CN3P_I9_N2: length 14.6
  TOP w0.66: D1.1 42.22,45.82 43.08,45.82
  TOP w1.651: P2.2 52.51,42.98 52.32,43.17
  TOP w2.032: 43.08,45.82 49.67,45.82 52.32,43.17
UNNAMED_2_CN3P_I9_N3: length 13.3
  TOP w0.66: D2.2 66.77,45.52 65.45,45.52
  TOP w1.651: 55.08,45.52 P2.3
  TOP w2.032: 65.45,45.52 55.08,45.52
UNNAMED_2_CN3P_I10_N2: length 14.6
  TOP w0.66: 99.98,45.82 99.12,45.82 D3.1
  TOP w1.651: P4.2 109.41,42.98 109.22,43.17
  TOP w2.032: 99.98,45.82 106.57,45.82 109.22,43.17
UNNAMED_2_CN3P_I10_N3: length 13.3
  TOP w0.66: D4.2 123.67,45.52 122.35,45.52
  TOP w1.651: 111.98,45.52 P4.3
  TOP w2.032: 122.35,45.52 111.98,45.52
UNNAMED_3_CN2P_I10_N1: length 30.2
  TOP w0.66: D5.2 38.31,28.33 37.01,28.33
  TOP w1.778: 10.38,28.33 P5.1
  TOP w2.032: 10.38,28.33 37.01,28.33 37.01,28.33
UNNAMED_3_CN3P_I5_N2: length 14.6
  TOP w0.66: D7.1 99.12,28.63 99.98,28.63
  TOP w1.651: 109.22,25.98 109.41,25.79 P8.2
  TOP w2.032: 99.98,28.63 106.57,28.63 109.22,25.98
UNNAMED_3_CN3P_I5_N3: length 13.3
  TOP w0.66: 122.35,28.33 123.67,28.33 D8.2
  TOP w1.651: 111.98,28.33 P8.3
  TOP w2.032: 122.35,28.33 111.98,28.33
UNNAMED_3_CN3P_I6_N2: length 14.6
  TOP w0.66: 71.53,28.63 70.67,28.63 D6.1
  TOP w1.651: P7.2 80.96,25.79 80.77,25.98
  TOP w2.032: 80.77,25.98 78.12,28.63 71.53,28.63
UNNAMED_3_CN3P_I6_N3: length 13.3
  TOP w0.66: D7.2 95.22,28.33 93.9,28.33
  TOP w1.651: 83.53,28.33 P7.3
  TOP w2.032: 93.9,28.33 83.53,28.33
UNNAMED_3_CN3P_I12_N2: length 14.6
  TOP w0.66: 43.08,28.63 42.22,28.63 D5.1
  TOP w1.651: 52.32,25.98 52.51,25.79 P6.2
  TOP w2.032: 52.32,25.98 49.67,28.63 43.08,28.63
UNNAMED_3_CN3P_I12_N3: length 13.3
  TOP w0.66: 65.45,28.33 66.77,28.33 D6.2
  TOP w1.651: 55.08,28.33 P6.3
  TOP w2.032: 65.45,28.33 55.08,28.33
UNNAMED_4_CN2P_I13_N1: length 30.2
  TOP w0.66: 36.13,10.82 36.26,10.94 38.51,10.94 D9.2
  TOP w1.778: 10.4,10.82 P9.1
  TOP w2.032: 36.13,10.82 10.4,10.82
UNNAMED_4_CN3P_I4_N2: length 14.6
  TOP w0.66: D11.1 99.12,11.44 99.98,11.44
  TOP w1.651: 109.22,8.79 109.41,8.6 P12.2
  TOP w2.032: 99.98,11.44 106.57,11.44 109.22,8.79
UNNAMED_4_CN3P_I4_N3: length 13.3
  TOP w0.66: D12.2 123.66,11.14 122.34,11.14
  TOP w1.651: 111.98,11.14 P12.3
  TOP w2.032: 122.34,11.14 111.98,11.14
UNNAMED_4_CN3P_I9_N2: length 14.6
  TOP w0.66: D10.1 70.67,11.44 71.53,11.44
  TOP w1.651: P11.2 80.96,8.6 80.77,8.79
  TOP w2.032: 80.77,8.79 78.12,11.44 71.53,11.44
UNNAMED_4_CN3P_I9_N3: length 13.3
  TOP w0.66: 93.89,11.14 95.21,11.14 D11.2
  TOP w1.651: 83.53,11.14 P11.3
  TOP w2.032: 93.89,11.14 83.53,11.14
UNNAMED_4_CN3P_I11_N2: length 14.6
  TOP w0.66: 43.08,11.44 42.22,11.44 D9.1
  TOP w1.651: P10.2 52.52,8.6 52.33,8.79
  TOP w2.032: 43.08,11.44 49.67,11.44 52.33,8.79
UNNAMED_4_CN3P_I11_N3: length 13.3
  TOP w0.66: 65.45,11.14 66.77,11.14 D10.2
  TOP w1.651: 55.08,11.14 P10.3
  TOP w2.032: 65.45,11.14 55.08,11.14

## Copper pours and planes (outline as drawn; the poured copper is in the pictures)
AGND_A on TOP: 1.27,34.95 1.27,50.3 151.14,50.3 151.14,34.95
AGND_A on BOTTOM: 1.27,34.95 1.27,50.3 151.14,50.3 151.14,34.95
AGND_B on TOP, BOTTOM: 1.27,33.68 151.14,33.68 151.14,17.8 1.27,17.8
AGND_C on TOP: 1.27,16.53 151.14,16.55 151.14,1.27 1.27,1.27
AGND_C on BOTTOM: 1.27,16.53 151.14,16.55 151.14,1.27 1.27,1.27

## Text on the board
BOTTOM: SECONDARY SIDE | 08-047299 REV A
User.Comments: CR_LED_2 | CR_LED_3 | CR_LED_4 | 4.    FOLLOW THE ASSEMBLY AND HANDLING INFORMATION DOCUMENT | FOUND ON www.lumileds.com/uploads/252/AB32-pdf.
TOP: PRIMARY SIDE | 08-047299 REV A
Ref Des/Silkscreen Top: RLED1 | GLED1 | BLED1 | GND | RLED2 | GLED2 | BLED2 | BLED3 | RLED3 | GLED3 | GLED4 | RLED4 | BLED4 | VB | VR- | VB- | VR | VG | VG- | CFTL-LED BAR | +
DIMENSION: (REF) | DIA MAX
PAGE_OUTLINE: EVAL-CFTL-LED BAR
User.15: THICKNESS OF .003 INCH.
User.45: FIGURE | SIZE | 10.0 | 20.0 | 45.0 | 50.0 | 125.0 | PLATED | NON-PLATED | FINISHED HOLES IN MILS | ALL UNITS ARE IN MILS | QTY | 24 | 1124 | 27 | 6 | 4 | TOLERANCE/NOTES
